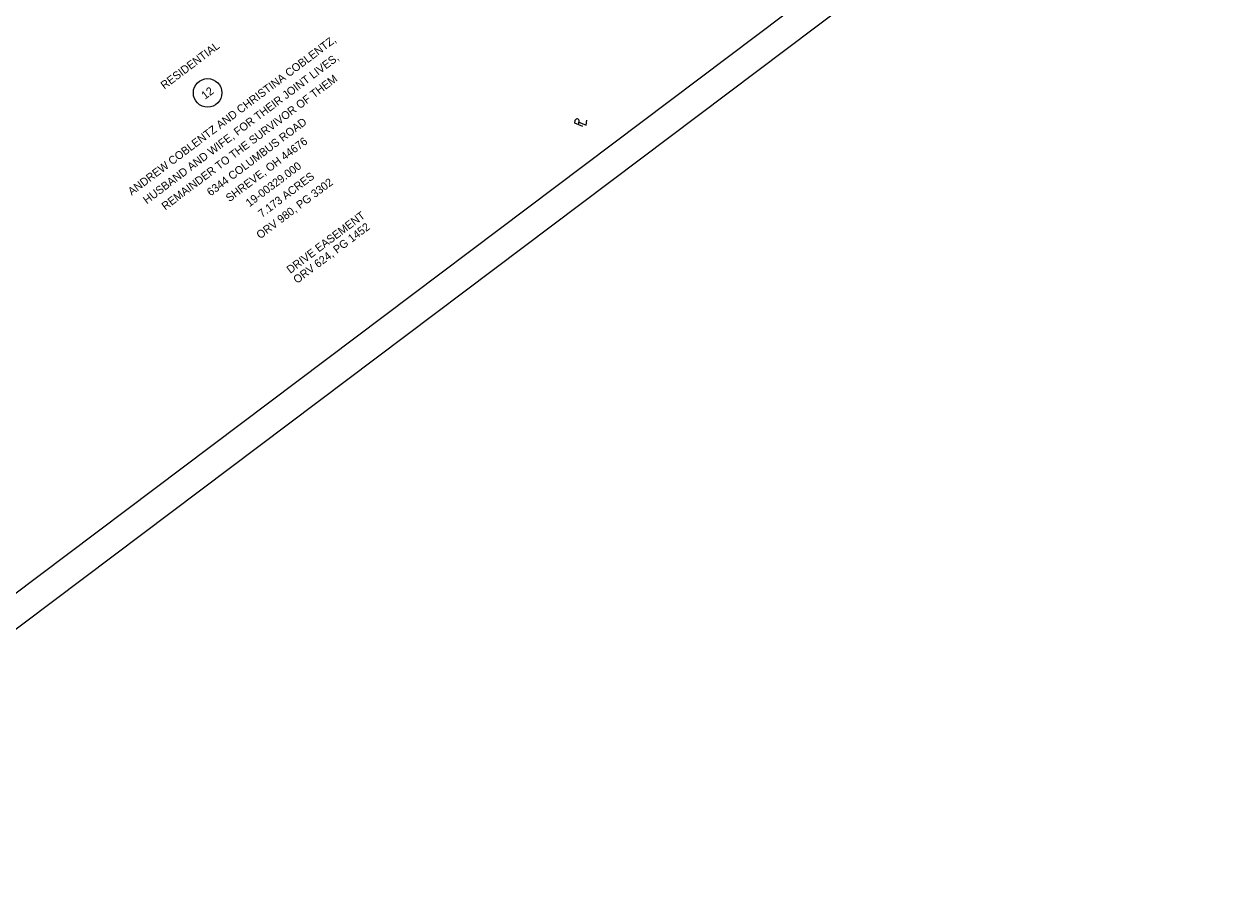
# Model space of a CAD drawing. Extents: x 120163 to 120971, y 463167 to 463927.
# Drawn here: x 120550.8 to 120971.3, y 463166.8 to 463468.7 of the extents above; entities that cross this region are included whole.
import ezdxf

# ---------------------------------------------------------------- set-up
doc = ezdxf.new("R2010")
doc.units = 0
for name, color, linetype in [('GE_X_Alignment', 7, 'Continuous'), ('RD_X_Cells', 7, 'Continuous'), ('SV_P_Mon_Cells_Set', 7, 'Continuous'), ('SV_X_Mon_Cells_Found', 7, 'Continuous')]:
    doc.layers.add(name, color=color, linetype=linetype)

msp = doc.modelspace()

# ---------------------------------------------------------------- linework, layer by layer
at = {"layer": 'GE_X_Alignment'}
for p, q in [((120744.8, 463433.4), (120744.98, 463434.69)), ((120745.53, 463434.11), (120745.53, 463434.11))]:
    msp.add_line(p, q, dxfattribs=at)
for points in [[(120746.32, 463432.77), (120743.49, 463433.95), (120743.64, 463434.98)], [(120744.62, 463434.51), (120747.44, 463433.31), (120747.68, 463435.04)]]:
    msp.add_lwpolyline(points, dxfattribs=at)
msp.add_arc((120744.3, 463434.78), 0.69, 352.4541, 163.3112, dxfattribs=at)
at = {"layer": 'RD_X_Cells'}
msp.add_lwpolyline([(120428.08, 463166.76), (120971.27, 463575.83), (120706.58, 463927.31), (120163.39, 463518.23)], close=True, dxfattribs=at)
at = {"layer": 'SV_P_Mon_Cells_Set'}
msp.add_circle((120615.03, 463444.59), 5, dxfattribs=at)
at = {"layer": 'SV_X_Mon_Cells_Found'}
msp.add_lwpolyline([(120193.37, 463528.29), (120704.61, 463913.3), (120957.27, 463577.8), (120446.03, 463192.79)], close=True, dxfattribs=at)

# ---------------------------------------------------------------- texts
at = {"layer": 'SV_P_Mon_Cells_Set'}
for s, p in [('ANDREW COBLENTZ AND CHRISTINA COBLENTZ,', (120588.47, 463408.56)), ('RESIDENTIAL', (120599.91, 463445.72)), ('HUSBAND AND WIFE, FOR THEIR JOINT LIVES,', (120593.77, 463405.55)), ('REMAINDER TO THE SURVIVOR OF THEM', (120600.23, 463403.4)), ('12', (120614.14, 463442.17)), ('6344 COLUMBUS ROAD', (120616.08, 463408.33)), ('SHREVE, OH 44676', (120622.68, 463406.29)), ('19-00329.000', (120629.66, 463404.54)), ('ORV 980, PG 3302', (120633.4, 463393.33)), ('7.173 ACRES', (120634.03, 463400.82)), ('DRIVE EASEMENT', (120643.96, 463381.2)), ('ORV 624, PG 1452', (120646.32, 463377.71))]:
    msp.add_text(s, height=2.8, rotation=36.9831, dxfattribs=at).set_placement(p)

doc.saveas('drawing.dxf')
